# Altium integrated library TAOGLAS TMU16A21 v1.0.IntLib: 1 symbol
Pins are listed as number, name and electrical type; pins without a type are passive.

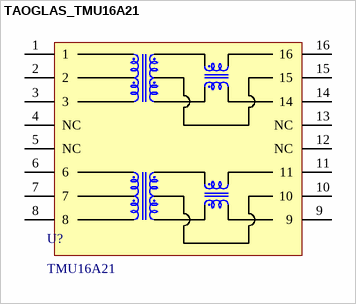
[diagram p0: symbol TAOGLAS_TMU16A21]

## TAOGLAS_TMU16A21
designator U?, comment TMU16A21
Transformer with Common Mode Choke for Battery Management System 16 pin SMT; ComponentLibStatus: Created; MFG: Taoglas; Temp_High: +85C; Temp_Low: -40C
footprint TAOGLAS_TMU16A21 (Transformer with Common Mode Choke for Battery Management System 16 pin SMT)
pins: 1, 2, 3, 4 NC, 5 NC, 6, 7, 8, 9, 10, 11, 12 NC, 13 NC, 14, 15, 16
